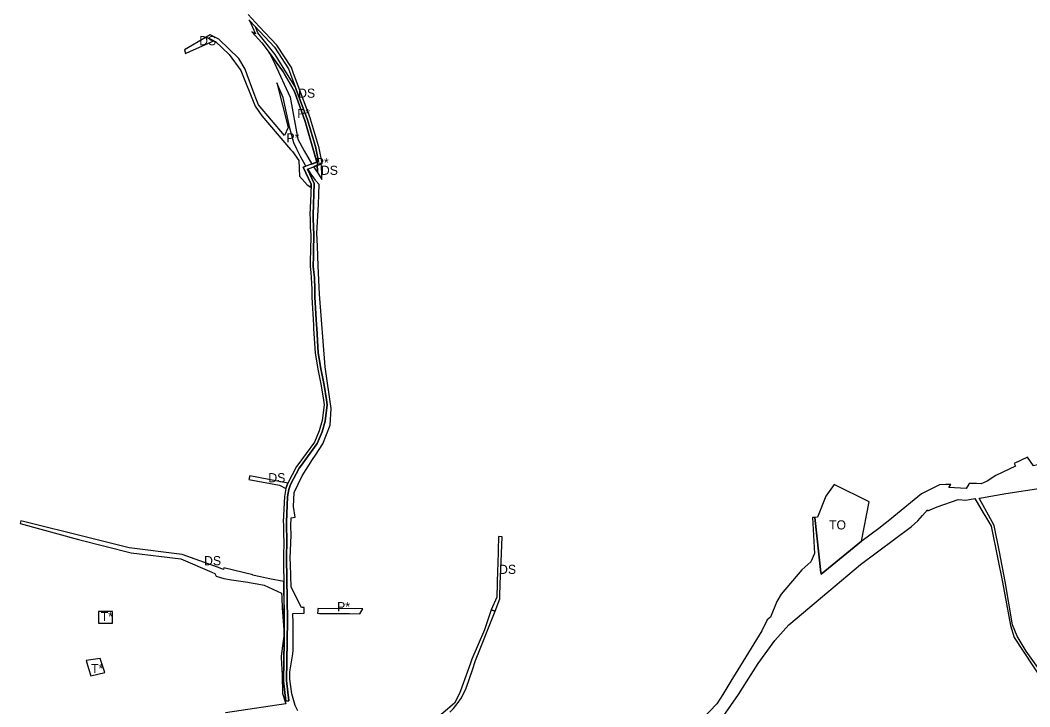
# Model space of a CAD drawing. Extents: x -477304 to -465641, y -1159113 to -1149285.
# Drawn here: x -473428 to -472433, y -1153624 to -1152947 of the extents above; entities that cross this region are included whole.
import ezdxf

# ---------------------------------------------------------------- set-up
doc = ezdxf.new("R2010")
doc.units = 0
for name, color, linetype in [('17', 7, 'Continuous'), ('19', 7, 'Continuous'), ('34', 7, 'Continuous'), ('35', 7, 'Continuous'), ('4', 7, 'Continuous')]:
    doc.layers.add(name, color=color, linetype=linetype)

msp = doc.modelspace()

# ---------------------------------------------------------------- linework, layer by layer
at = {"layer": '17'}
for p, q in [((-473348.92, -1153575.87), (-473362.76, -1153577.97)), ((-473362.76, -1153577.97), (-473360.31, -1153585.83)), ((-473345.22, -1153586.76), (-473348.92, -1153575.87)), ((-473360.31, -1153585.83), (-473358.01, -1153593.19)), ((-473344.19, -1153589.79), (-473345.22, -1153586.76)), ((-473358.01, -1153593.19), (-473344.19, -1153589.79))]:
    msp.add_line(p, q, dxfattribs=at)
msp.add_lwpolyline([(-473350.44, -1153541.27), (-473336.74, -1153541.27), (-473336.74, -1153529.83), (-473350.44, -1153529.83), (-473350.44, -1153541.27)], dxfattribs=at)
at = {"layer": '19'}
for p, q in [((-472634.3, -1153416.17), (-472642.51, -1153436.87)), ((-472599.1, -1153460.35), (-472591.8, -1153421.54)), ((-472642.51, -1153436.87), (-472645.15, -1153436.94)), ((-472645.15, -1153436.94), (-472639.09, -1153491.3)), ((-472638.92, -1153492.84), (-472599.1, -1153460.35)), ((-472639.09, -1153491.3), (-472639.06, -1153491.59)), ((-472639.06, -1153491.59), (-472638.92, -1153492.84))]:
    msp.add_line(p, q, dxfattribs=at)
msp.add_lwpolyline([(-472591.8, -1153421.54), (-472626.13, -1153404.59), (-472634.3, -1153416.17)], dxfattribs=at)
at = {"layer": '34'}
for p, q in [((-473240.63, -1152961.29), (-473244.47, -1152963.52)), ((-473231.92, -1152965.43), (-473240.63, -1152961.29)), ((-473244.47, -1152963.52), (-473237.02, -1152967.24)), ((-473237.02, -1152967.24), (-473235.51, -1152967.79)), ((-473235.51, -1152967.79), (-473222, -1152980.76)), ((-473212.28, -1152984.68), (-473231.92, -1152965.43)), ((-473172.84, -1152991.76), (-473182.49, -1152978.74)), ((-473182.49, -1152978.74), (-473177.19, -1152989.28)), ((-473177.19, -1152989.28), (-473161.71, -1153022.74)), ((-473168.92, -1152997.26), (-473172.84, -1152991.76)), ((-473174.8, -1153008.65), (-473163.76, -1153052.51)), ((-473192.94, -1153030.35), (-473195.72, -1153023.58)), ((-473167.33, -1153060.5), (-473192.94, -1153030.35)), ((-473161.71, -1153022.74), (-473154.36, -1153064.28)), ((-473189.65, -1153041.26), (-473161.43, -1153074.3)), ((-473135.5, -1153086.83), (-473147.06, -1153046.72)), ((-473163.76, -1153052.51), (-473167.33, -1153060.5)), ((-473158.19, -1153067.69), (-473162.23, -1153053.32)), ((-473155.33, -1153074.04), (-473158.19, -1153067.69)), ((-473161.43, -1153074.3), (-473159.67, -1153076.36)), ((-473159.67, -1153076.36), (-473153.35, -1153085.32)), ((-473153.35, -1153085.32), (-473152.47, -1153100.47)), ((-473140.36, -1153088.67), (-473135.5, -1153086.83)), ((-473135.11, -1153089.89), (-473138.77, -1153091.27)), ((-473138.77, -1153091.27), (-473134.97, -1153096.87)), ((-473134.95, -1153095.21), (-473135.11, -1153089.89)), ((-473152.47, -1153100.47), (-473145.12, -1153109.1)), ((-473144.55, -1153093.46), (-473144.8, -1153093.55)), ((-473144.8, -1153093.55), (-473138.27, -1153107.79)), ((-473141.18, -1153098.58), (-473144.55, -1153093.46)), ((-473140.15, -1153099.94), (-473141.18, -1153098.58)), ((-473134.97, -1153096.87), (-473134.95, -1153095.21)), ((-473145.12, -1153109.1), (-473141.4, -1153111.52)), ((-473141.4, -1153111.52), (-473141.29, -1153108.4)), ((-473133.32, -1153108.97), (-473136.55, -1153105.11)), ((-473134.01, -1153128.7), (-473133.32, -1153108.97)), ((-473135.42, -1153156.7), (-473134.01, -1153128.7)), ((-473139.01, -1153151.15), (-473138.56, -1153158.09)), ((-473134.94, -1153169.65), (-473135.42, -1153156.7)), ((-473134.23, -1153189.01), (-473134.94, -1153169.65)), ((-473135.71, -1153250.58), (-473134.34, -1153274.77)), ((-473125.4, -1153326.12), (-473127.48, -1153342)), ((-473125.97, -1153320.94), (-473125.4, -1153326.12)), ((-473129.55, -1153364.6), (-473122.42, -1153345.93)), ((-473136.86, -1153375.45), (-473129.55, -1153364.6)), ((-473139.87, -1153380.02), (-473136.86, -1153375.45)), ((-473149.93, -1153396.13), (-473139.87, -1153380.02)), ((-473157.77, -1153412.47), (-473149.93, -1153396.13)), ((-473163.28, -1153409.4), (-473164.52, -1153416.71)), ((-473164.52, -1153416.71), (-473165.57, -1153441.5)), ((-473158.55, -1153426.36), (-473157.77, -1153412.47)), ((-473156.98, -1153436.56), (-473158.55, -1153426.36)), ((-473165.46, -1153445.04), (-473165.15, -1153459.29)), ((-473161.82, -1153477.17), (-473160.84, -1153454.56)), ((-473165.15, -1153459.29), (-473165.5, -1153477)), ((-473165.5, -1153477), (-473164.6, -1153538.06)), ((-473161.61, -1153483.42), (-473161.82, -1153477.17)), ((-473160.75, -1153505.73), (-473161.61, -1153483.42)), ((-473150.73, -1153525.91), (-473160.75, -1153505.73)), ((-473167.75, -1153528.04), (-473169.64, -1153526.92)), ((-473169.64, -1153526.92), (-473169.47, -1153530.41)), ((-473167.6, -1153538.1), (-473167.75, -1153528.04)), ((-473148.08, -1153525.89), (-473150.73, -1153525.91)), ((-473148.02, -1153531.38), (-473148.08, -1153525.89)), ((-473134.51, -1153526.63), (-473134.71, -1153528.63)), ((-473090.31, -1153527.01), (-473134.51, -1153526.63)), ((-473093.2, -1153532.01), (-473090.31, -1153527.01)), ((-472963.72, -1153528.03), (-472970.34, -1153547.67)), ((-472960.09, -1153529.4), (-472963.72, -1153528.03)), ((-473167.73, -1153552.85), (-473167.6, -1153538.1)), ((-473164.6, -1153538.06), (-473164.79, -1153559.2)), ((-473132.87, -1153531.51), (-473103.49, -1153531.75)), ((-473103.49, -1153531.75), (-473093.2, -1153532.01)), ((-472979.18, -1153577.85), (-472960.09, -1153529.4)), ((-473158.8, -1153568.1), (-473159.02, -1153541.24)), ((-472970.34, -1153547.67), (-472982.77, -1153576.58)), ((-473167.81, -1153551.83), (-473169.6, -1153565.96)), ((-473167.79, -1153559.17), (-473167.78, -1153558)), ((-473167.78, -1153558), (-473167.73, -1153552.85)), ((-473169.6, -1153565.96), (-473170.63, -1153574.12)), ((-473164.79, -1153559.2), (-473165.32, -1153597.73)), ((-473170.63, -1153574.12), (-473170.75, -1153575.08)), ((-473170.75, -1153575.08), (-473169.85, -1153592.86)), ((-472982.77, -1153576.58), (-472984.27, -1153580.52)), ((-472982.37, -1153587.34), (-472979.18, -1153577.85)), ((-472988.59, -1153605.31), (-472982.37, -1153587.34)), ((-473165.32, -1153597.73), (-473162.99, -1153617.75)), ((-473162.27, -1153596.29), (-473162.12, -1153589.11)), ((-473160.21, -1153610.76), (-473162.27, -1153596.29)), ((-472993.16, -1153614.87), (-472988.59, -1153605.31)), ((-473156.86, -1153622.28), (-473160.21, -1153610.76)), ((-472997.22, -1153620.67), (-472993.16, -1153614.87)), ((-473165.99, -1153620.61), (-473225.37, -1153629.58)), ((-473154.31, -1153627.53), (-473156.86, -1153622.28)), ((-472998.61, -1153622.41), (-472997.22, -1153620.67))]:
    msp.add_line(p, q, dxfattribs=at)
for points in [[(-473222, -1152980.76), (-473210.25, -1152996.33), (-473196.23, -1153031.56), (-473189.65, -1153041.26)], [(-473195.72, -1153023.58), (-473198.54, -1153015.77), (-473204.09, -1153000.76), (-473206.3, -1152995.03), (-473212.28, -1152984.68)], [(-473147.06, -1153046.72), (-473157.6, -1153017.12), (-473168.92, -1152997.26)], [(-473162.23, -1153053.32), (-473168.77, -1153022.95), (-473174.8, -1153008.65)], [(-473154.36, -1153064.28), (-473147.88, -1153075.56), (-473140.69, -1153088.09), (-473140.36, -1153088.67)], [(-473146.25, -1153090.89), (-473147.1, -1153089.6), (-473151.27, -1153081.85), (-473155.33, -1153074.04)], [(-473141.29, -1153108.4), (-473148.86, -1153091.88), (-473146.25, -1153090.89)], [(-473136.55, -1153105.11), (-473136.96, -1153104.52), (-473140.15, -1153099.94)], [(-473138.27, -1153107.79), (-473139.32, -1153138.61), (-473139.24, -1153141.81), (-473139.01, -1153151.15)], [(-473138.56, -1153158.09), (-473138.76, -1153175), (-473138.88, -1153176.65), (-473138.98, -1153181.31)], [(-473138.98, -1153181.31), (-473139.09, -1153187.33), (-473139.14, -1153189.68)], [(-473139.14, -1153189.68), (-473138.56, -1153195.31), (-473137.98, -1153200.65), (-473137.65, -1153211.89), (-473137.42, -1153219.79), (-473135.9, -1153247.15), (-473135.71, -1153250.58)], [(-473127.39, -1153288.54), (-473132.85, -1153216.99), (-473134.23, -1153189.01)], [(-473134.34, -1153274.77), (-473131.15, -1153292.12), (-473130.95, -1153293.58), (-473128.92, -1153303.36), (-473128.34, -1153306.77), (-473125.97, -1153320.94)], [(-473122.42, -1153345.93), (-473121.6, -1153329.7), (-473127.39, -1153288.54)], [(-473127.48, -1153342), (-473130.3, -1153352.69), (-473135.11, -1153364.13), (-473151.81, -1153386.83), (-473153, -1153388.45)], [(-473153, -1153388.45), (-473161.35, -1153404.52), (-473163.28, -1153409.4)], [(-473160.84, -1153454.56), (-473161.1, -1153445.41), (-473160.9, -1153437.24), (-473156.98, -1153436.56)], [(-473165.57, -1153441.5), (-473165.52, -1153443.76), (-473165.46, -1153445.04)], [(-473134.71, -1153528.63), (-473135, -1153531.49), (-473132.87, -1153531.51)], [(-473169.47, -1153530.41), (-473168.06, -1153547.71), (-473167.81, -1153551.83)], [(-473159.02, -1153541.24), (-473159.1, -1153531.78), (-473148.02, -1153531.38)], [(-473162.99, -1153617.75), (-473165.97, -1153618.09), (-473168.32, -1153597.89), (-473167.79, -1153559.17)], [(-473162.12, -1153589.11), (-473159.33, -1153571.45), (-473158.8, -1153568.1)], [(-472984.27, -1153580.52), (-472992.74, -1153604.15), (-472995.01, -1153610.48)], [(-473169.85, -1153592.86), (-473169.22, -1153610.37), (-473165.99, -1153620.61)], [(-472995.01, -1153610.48), (-473000.11, -1153620.09), (-473022.18, -1153638.97)], [(-473004.62, -1153628.85), (-473000.99, -1153625.4), (-472998.61, -1153622.41)]]:
    msp.add_lwpolyline(points, dxfattribs=at)
at = {"layer": '35'}
for p, q in [((-473196.6, -1152952.79), (-473201.72, -1152947.29)), ((-473199.45, -1152958.39), (-473189.64, -1152969.09)), ((-473196.01, -1152953.42), (-473196.6, -1152952.79)), ((-473244.47, -1152963.52), (-473265.86, -1152975.97)), ((-473260.01, -1152977.49), (-473237.02, -1152967.24)), ((-473237.02, -1152967.24), (-473244.47, -1152963.52)), ((-473189.64, -1152969.09), (-473182.49, -1152978.74)), ((-473182.49, -1152978.74), (-473172.84, -1152991.76)), ((-473164.41, -1153000.45), (-473176.7, -1152980.7)), ((-473172.84, -1152991.76), (-473168.92, -1152997.26)), ((-473156.66, -1153012.9), (-473164.41, -1153000.45)), ((-473155.83, -1153015.17), (-473156.66, -1153012.9)), ((-473144.76, -1153045.17), (-473155.83, -1153015.17)), ((-473147.06, -1153046.72), (-473135.5, -1153086.83)), ((-473135.5, -1153086.83), (-473133.81, -1153086.19)), ((-473132.75, -1153088.99), (-473135.11, -1153089.89)), ((-473135.11, -1153089.89), (-473134.95, -1153095.21)), ((-473131.37, -1153088.47), (-473132.75, -1153088.99)), ((-473131.1, -1153090.96), (-473131.37, -1153088.47)), ((-473130.75, -1153099.05), (-473131.1, -1153090.96)), ((-473134.95, -1153095.21), (-473134.97, -1153096.87)), ((-473134.97, -1153096.87), (-473130.57, -1153103.75)), ((-473130.69, -1153100.62), (-473130.75, -1153099.05)), ((-473130.57, -1153103.75), (-473130.69, -1153100.62)), ((-472435.56, -1153377.43), (-472448.76, -1153383.97)), ((-473201.64, -1153396.09), (-473202.54, -1153399.69)), ((-472466.75, -1153395.7), (-472475.49, -1153401.37)), ((-473202.54, -1153399.69), (-473172.32, -1153405.22)), ((-473172.32, -1153405.22), (-473166.19, -1153408.59)), ((-472522.48, -1153404.96), (-472540.01, -1153413.88)), ((-472516.08, -1153404.43), (-472522.48, -1153404.96)), ((-472511.05, -1153404.47), (-472516.08, -1153404.43)), ((-472513.04, -1153407.48), (-472511.05, -1153404.47)), ((-472496.01, -1153408.35), (-472513.04, -1153407.48)), ((-472493.39, -1153404.24), (-472496.01, -1153408.35)), ((-472493.04, -1153403.7), (-472493.39, -1153404.24)), ((-472490.38, -1153403.62), (-472493.04, -1153403.7)), ((-472485.92, -1153403.59), (-472490.38, -1153403.62)), ((-472481.3, -1153403.98), (-472485.92, -1153403.59)), ((-472475.49, -1153401.37), (-472481.3, -1153403.98)), ((-472540.01, -1153413.88), (-472567.2, -1153436.1)), ((-472524.8, -1153426.66), (-472503.97, -1153419.44)), ((-472503.97, -1153419.44), (-472496.45, -1153419.95)), ((-472496.45, -1153419.95), (-472492.71, -1153419.15)), ((-472492.71, -1153419.15), (-472487.6, -1153418.46)), ((-472487.6, -1153418.46), (-472479.25, -1153432.55)), ((-472483.33, -1153417.88), (-472480.91, -1153417.55)), ((-472468.64, -1153444.9), (-472483.33, -1153417.88)), ((-472526.95, -1153427.49), (-472524.8, -1153426.66)), ((-472645.15, -1153436.94), (-472647.42, -1153437)), ((-472647.42, -1153437), (-472645.34, -1153472.65)), ((-472639.09, -1153491.3), (-472645.15, -1153436.94)), ((-472567.2, -1153436.1), (-472569.56, -1153437.97)), ((-472543.76, -1153440.46), (-472539.21, -1153435.1)), ((-472539.21, -1153435.1), (-472534.22, -1153429.45)), ((-472479.25, -1153432.55), (-472476.23, -1153437.69)), ((-472476.23, -1153437.69), (-472471.49, -1153445.75)), ((-473427.02, -1153440.19), (-473427.69, -1153442.92)), ((-473427.69, -1153442.92), (-473370.32, -1153458.88)), ((-473358.35, -1153457.38), (-473427.02, -1153440.19)), ((-472600.17, -1153483.52), (-472549.84, -1153445.85)), ((-472549.84, -1153445.85), (-472543.76, -1153440.46)), ((-472471.49, -1153445.75), (-472465.3, -1153476.42)), ((-473370.32, -1153458.88), (-473318.27, -1153471.9)), ((-473320.45, -1153466.86), (-473358.35, -1153457.38)), ((-472954.26, -1153488.84), (-472953.03, -1153455.95)), ((-473268.14, -1153473.57), (-473320.45, -1153466.86)), ((-473318.27, -1153471.9), (-473269.46, -1153477.67)), ((-473269.46, -1153477.67), (-473238.86, -1153490.85)), ((-473233.5, -1153485.96), (-473268.14, -1153473.57)), ((-472465.3, -1153476.42), (-472460.4, -1153500.7)), ((-473227.33, -1153488.17), (-473233.5, -1153485.96)), ((-473227.08, -1153486.79), (-473227.33, -1153488.17)), ((-473198.7, -1153493.41), (-473227.08, -1153486.79)), ((-472957.56, -1153488.69), (-472958.42, -1153515.59)), ((-472957.42, -1153483.23), (-472957.56, -1153488.69)), ((-472954.53, -1153493.88), (-472954.26, -1153488.84)), ((-472631.22, -1153509.61), (-472600.17, -1153483.52)), ((-473238.86, -1153490.85), (-473235.91, -1153492.12)), ((-473227.26, -1153497.14), (-473219.48, -1153498.36)), ((-473219.48, -1153498.36), (-473203.55, -1153500.87)), ((-473198.81, -1153494.01), (-473198.7, -1153493.41)), ((-473191.01, -1153495.65), (-473198.81, -1153494.01)), ((-473182.2, -1153497.44), (-473191.01, -1153495.65)), ((-473168.16, -1153500.29), (-473182.2, -1153497.44)), ((-472955.33, -1153513.14), (-472954.53, -1153493.88)), ((-472639.06, -1153491.59), (-472639.09, -1153491.3)), ((-472638.92, -1153492.84), (-472639.06, -1153491.59)), ((-473194.46, -1153502.55), (-473187.3, -1153503.87)), ((-473167.75, -1153528.04), (-473168.16, -1153500.29)), ((-472460.4, -1153500.7), (-472452.55, -1153543.43)), ((-472450.57, -1153542.7), (-472457.61, -1153500.07)), ((-472958.42, -1153515.59), (-472963.72, -1153528.03)), ((-472960.09, -1153529.4), (-472955.51, -1153517.37)), ((-472955.51, -1153517.37), (-472955.33, -1153513.14)), ((-472963.72, -1153528.03), (-472960.09, -1153529.4)), ((-472691.92, -1153538.07), (-472697.27, -1153548.91)), ((-472688.76, -1153535.35), (-472691.92, -1153538.07)), ((-472452.55, -1153543.43), (-472448.97, -1153555.47)), ((-472701, -1153581.01), (-472684.41, -1153558.25)), ((-472712.45, -1153598.91), (-472701, -1153581.01)), ((-472724.35, -1153592.35), (-472728.74, -1153600)), ((-472728.74, -1153600), (-472735.7, -1153611.46)), ((-472720.43, -1153611.39), (-472712.45, -1153598.91)), ((-472735.7, -1153611.46), (-472741.74, -1153620.6)), ((-472735.37, -1153633.17), (-472720.43, -1153611.39)), ((-472741.74, -1153620.6), (-472756.11, -1153635.72))]:
    msp.add_line(p, q, dxfattribs=at)
for points in [[(-473201.72, -1152947.29), (-473196.04, -1152960.33), (-473199.45, -1152958.39)], [(-473176.7, -1152980.7), (-473193.51, -1152959.46), (-473196.01, -1152953.42)], [(-473265.86, -1152975.97), (-473264.74, -1152979.6), (-473260.01, -1152977.49)], [(-473168.92, -1152997.26), (-473157.6, -1153017.12), (-473147.06, -1153046.72)], [(-473133.81, -1153086.19), (-473136.74, -1153071.37), (-473144.76, -1153045.17)], [(-472396.13, -1153384.85), (-472410.35, -1153383.18), (-472419.4, -1153383.38), (-472429.87, -1153385.96), (-472435.56, -1153377.43)], [(-472448.76, -1153383.97), (-472447.54, -1153386.52), (-472466.75, -1153395.7)], [(-473166.19, -1153408.59), (-473164.08, -1153403.27), (-473201.64, -1153396.09)], [(-472480.91, -1153417.55), (-472456.9, -1153413.45), (-472422.73, -1153408.13)], [(-472534.22, -1153429.45), (-472533.71, -1153430.54), (-472526.95, -1153427.49)], [(-472569.56, -1153437.97), (-472582.24, -1153448.04), (-472598.52, -1153459.89)], [(-472457.61, -1153500.07), (-472463.32, -1153470.83), (-472468.64, -1153444.9)], [(-472953.03, -1153455.95), (-472956.69, -1153455.89), (-472957.42, -1153483.23)], [(-472598.52, -1153459.89), (-472599.1, -1153460.35), (-472638.92, -1153492.84)], [(-472645.34, -1153472.65), (-472649.03, -1153480.84), (-472657.93, -1153488.62), (-472678.3, -1153512.65)], [(-473235.91, -1153492.12), (-473234.57, -1153494.83), (-473230.35, -1153496.16), (-473227.26, -1153497.14)], [(-473203.55, -1153500.87), (-473200.38, -1153501.46), (-473194.46, -1153502.55)], [(-473187.3, -1153503.87), (-473170.4, -1153511.55), (-473170.19, -1153515.72), (-473169.64, -1153526.92), (-473167.75, -1153528.04)], [(-472678.3, -1153512.65), (-472682.51, -1153519.7), (-472688.76, -1153535.35)], [(-472684.41, -1153558.25), (-472670.68, -1153542.77), (-472631.22, -1153509.61)], [(-472417.46, -1153596.38), (-472436.96, -1153568.79), (-472446.01, -1153554.12), (-472450.57, -1153542.7)], [(-472697.27, -1153548.91), (-472702.65, -1153557.35), (-472707.86, -1153565.88), (-472713.04, -1153574.44), (-472718.22, -1153582.99), (-472723.45, -1153591.52), (-472724.35, -1153592.35)], [(-472448.97, -1153555.47), (-472420.86, -1153597.75), (-472405, -1153623.89), (-472397.48, -1153635.48)]]:
    msp.add_lwpolyline(points, dxfattribs=at)
at = {"layer": '4'}
for p, q in [((-473202.53, -1152946.42), (-473196.6, -1152952.79)), ((-473163.31, -1152994.88), (-473161.37, -1153000.15)), ((-473161.37, -1153000.15), (-473155.83, -1153015.17)), ((-473158.79, -1152998.48), (-473160.62, -1152993.52)), ((-473155.83, -1153015.17), (-473144.76, -1153045.17)), ((-473133.83, -1153070.64), (-473140.86, -1153047.68)), ((-473133.7, -1153071.26), (-473133.83, -1153070.64)), ((-473130.41, -1153087.91), (-473133.7, -1153071.26)), ((-473144.8, -1153093.55), (-473132.75, -1153088.99)), ((-473132.75, -1153088.99), (-473130.38, -1153088.1)), ((-473130.38, -1153088.1), (-473130.41, -1153087.91)), ((-473138.27, -1153107.79), (-473144.8, -1153093.55)), ((-473142.01, -1153151.28), (-473141.56, -1153158.17)), ((-473141.56, -1153158.17), (-473141.76, -1153174.87)), ((-473138.56, -1153158.09), (-473139.01, -1153151.15)), ((-473141.88, -1153176.51), (-473141.98, -1153181.25)), ((-473141.76, -1153174.87), (-473141.88, -1153176.51)), ((-473141.98, -1153181.25), (-473142.09, -1153187.27)), ((-473140.98, -1153200.85), (-473140.65, -1153211.98)), ((-473134.34, -1153274.77), (-473135.71, -1153250.58)), ((-473137.32, -1153275.13), (-473134.11, -1153292.59)), ((-473131.87, -1153303.92), (-473131.3, -1153307.27)), ((-473127.48, -1153342), (-473125.4, -1153326.12)), ((-473125.4, -1153326.12), (-473125.97, -1153320.94)), ((-473155.56, -1153386.86), (-473164.08, -1153403.27)), ((-473164.52, -1153416.71), (-473163.28, -1153409.4)), ((-473165.57, -1153441.5), (-473164.52, -1153416.71)), ((-473165.15, -1153459.29), (-473165.46, -1153445.04)), ((-473168.23, -1153455.64), (-473168.15, -1153459.29)), ((-473168.15, -1153459.29), (-473168.5, -1153476.99)), ((-473165.5, -1153477), (-473165.15, -1153459.29)), ((-473168.5, -1153476.99), (-473167.6, -1153538.1)), ((-473164.6, -1153538.06), (-473165.5, -1153477)), ((-473167.6, -1153538.1), (-473167.73, -1153552.85)), ((-473164.79, -1153559.2), (-473164.6, -1153538.06)), ((-473167.78, -1153558), (-473167.79, -1153559.17)), ((-473167.73, -1153552.85), (-473167.78, -1153558)), ((-473165.32, -1153597.73), (-473164.79, -1153559.2)), ((-473162.99, -1153617.75), (-473165.32, -1153597.73))]:
    msp.add_line(p, q, dxfattribs=at)
for points in [[(-473160.62, -1152993.52), (-473175.02, -1152971.59), (-473192.31, -1152952.99), (-473203.16, -1152941.34)], [(-473196.6, -1152952.79), (-473177.39, -1152973.44), (-473163.31, -1152994.88)], [(-473140.86, -1153047.68), (-473141.82, -1153044.53), (-473141.92, -1153044.21), (-473158.79, -1152998.48)], [(-473144.76, -1153045.17), (-473136.74, -1153071.37), (-473133.81, -1153086.19)], [(-473133.81, -1153086.19), (-473148.86, -1153091.88), (-473141.29, -1153108.4), (-473141.62, -1153118.09)], [(-473139.01, -1153151.15), (-473139.24, -1153141.81), (-473139.32, -1153138.61), (-473138.27, -1153107.79)], [(-473141.62, -1153118.09), (-473142.32, -1153138.6), (-473142.24, -1153141.88), (-473142.01, -1153151.28)], [(-473138.98, -1153181.31), (-473138.88, -1153176.65), (-473138.76, -1153175), (-473138.56, -1153158.09)], [(-473142.09, -1153187.27), (-473142.14, -1153189.81), (-473141.54, -1153195.62), (-473140.98, -1153200.85)], [(-473139.14, -1153189.68), (-473139.09, -1153187.33), (-473138.98, -1153181.31)], [(-473135.71, -1153250.58), (-473135.9, -1153247.15), (-473137.42, -1153219.79), (-473137.65, -1153211.89), (-473137.98, -1153200.65), (-473138.56, -1153195.31), (-473139.14, -1153189.68)], [(-473140.65, -1153211.98), (-473140.42, -1153219.92), (-473138.9, -1153247.32), (-473138.71, -1153250.75), (-473137.32, -1153275.13)], [(-473125.97, -1153320.94), (-473128.34, -1153306.77), (-473128.92, -1153303.36), (-473130.95, -1153293.58), (-473131.15, -1153292.12), (-473134.34, -1153274.77)], [(-473134.11, -1153292.59), (-473133.91, -1153294.08), (-473131.87, -1153303.92)], [(-473131.3, -1153307.27), (-473128.94, -1153321.35), (-473128.42, -1153326.09), (-473130.43, -1153341.42), (-473133.15, -1153351.72), (-473137.74, -1153362.64)], [(-473153, -1153388.45), (-473151.81, -1153386.83), (-473135.11, -1153364.13), (-473130.3, -1153352.69), (-473127.48, -1153342)], [(-473137.74, -1153362.64), (-473154.23, -1153385.05), (-473155.56, -1153386.86)], [(-473163.28, -1153409.4), (-473161.35, -1153404.52), (-473153, -1153388.45)], [(-473164.08, -1153403.27), (-473166.19, -1153408.59), (-473167.51, -1153416.4)], [(-473167.51, -1153416.4), (-473168.57, -1153441.47), (-473168.52, -1153443.86)], [(-473168.52, -1153443.86), (-473168.46, -1153445.14), (-473168.23, -1153455.64)], [(-473165.46, -1153445.04), (-473165.52, -1153443.76), (-473165.57, -1153441.5)], [(-473167.79, -1153559.17), (-473168.32, -1153597.89), (-473165.97, -1153618.09), (-473162.99, -1153617.75)]]:
    msp.add_lwpolyline(points, dxfattribs=at)

# ---------------------------------------------------------------- texts
at = {"layer": '17'}
for p in [(-473348.34, -1153539.07), (-473357.93, -1153590.36)]:
    msp.add_text('T*', height=9, dxfattribs=at).set_placement(p)
at = {"layer": '19'}
msp.add_text('TO', height=9, dxfattribs=at).set_placement((-472631.15, -1153448.82))
at = {"layer": '34'}
for p in [(-473154.85, -1153043.33), (-473165.51, -1153067.33), (-473136.58, -1153091.83), (-473115.57, -1153529.45)]:
    msp.add_text('P*', height=9, dxfattribs=at).set_placement(p)
at = {"layer": '35'}
for p in [(-473251.44, -1152971.56), (-473153.98, -1153023.31), (-473131.55, -1153099.31), (-473183.31, -1153402.34), (-473246.58, -1153484.11), (-472956.08, -1153492.65)]:
    msp.add_text('DS', height=9, dxfattribs=at).set_placement(p)

doc.saveas('drawing.dxf')
